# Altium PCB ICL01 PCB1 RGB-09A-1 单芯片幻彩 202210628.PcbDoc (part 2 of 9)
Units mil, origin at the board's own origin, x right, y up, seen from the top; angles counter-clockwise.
Board outline 17436.43 x 6581.89 mil, 2 copper layers (Top Layer, Bottom Layer), stack 65.792 mil thick; 425 components, 516 nets, 1625 pads, 2772 vias.
Unrouted connection lines stored in the file: 1.
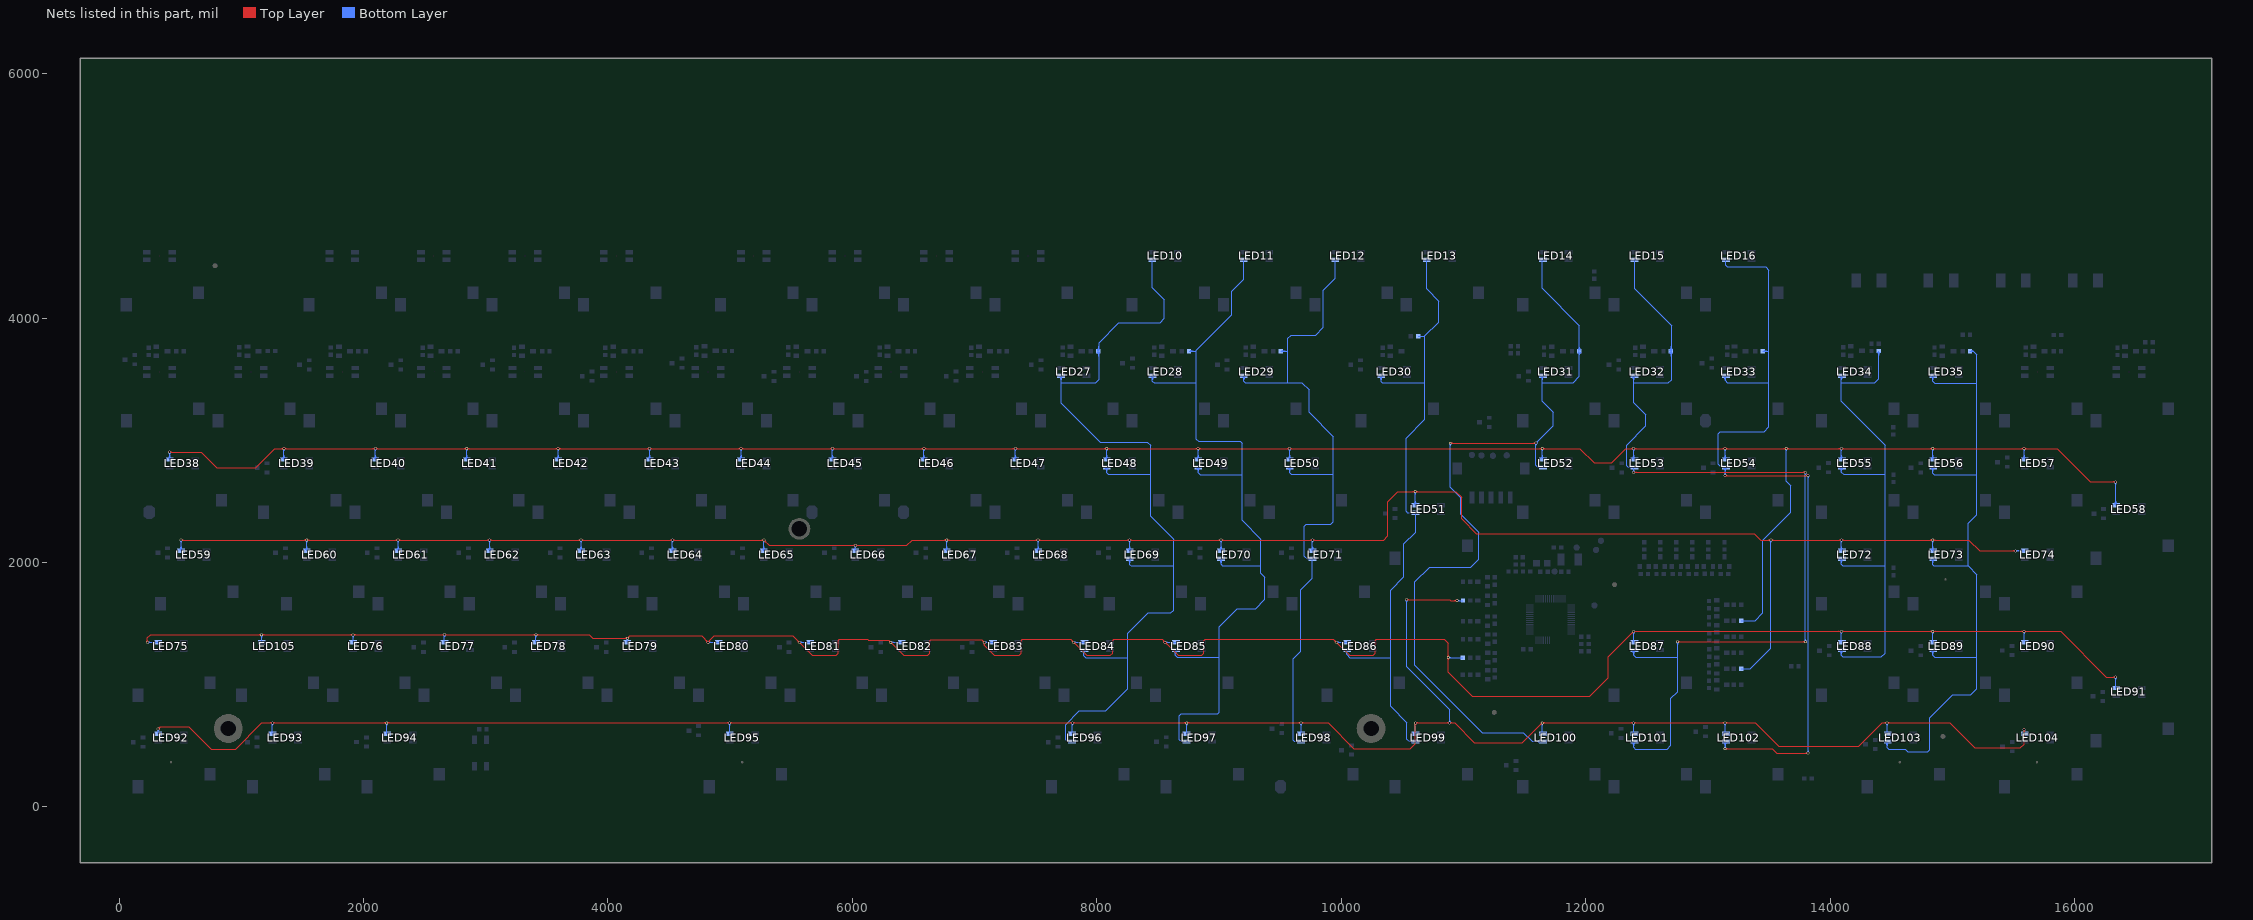
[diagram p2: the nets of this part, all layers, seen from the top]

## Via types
v1: diameter 23.62, hole 15.75, Top Layer to Bottom Layer, tented both sides, 2766 vias
v2: diameter 19.68, hole 11.81, Top Layer to Bottom Layer, tented both sides, 6 vias

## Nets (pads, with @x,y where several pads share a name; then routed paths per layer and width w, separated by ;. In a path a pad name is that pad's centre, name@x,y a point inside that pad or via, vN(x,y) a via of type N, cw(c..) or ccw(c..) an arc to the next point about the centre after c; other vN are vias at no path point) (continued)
BL2: LED38.B LED39.B LED40.B LED41.B LED42.B LED43.B LED44.B LED45.B LED46.B LED47.B LED48.B LED49.B LED50.B LED52.B LED53.B LED54.B LED55.B LED56.B LED57.B LED58.B RR8.2 | length 22619.1
  Top Layer w7.87: v1(414,2902.51) 674.24,2902.51 800.37,2776.38 1117.56,2776.38 1272.69,2931.5 v1(11644.32,2931.47) ; v1@419.57,2896.94 cw(c433.01,2883.5) 433.01,2902.51 cw(c433.01,2921.52) v1@419.57,2908.08 ; 1329.95,2931.5 cw(c1329.95,2912.38) v1@1343.47,2925.9 ; 1330.11,2931.5 ccw(c1330.11,2950.4) v1@1343.47,2937.04 ; v1@1354.61,2925.9 cw(c1368.13,2912.38) 1368.13,2931.5 ; v1@1354.61,2937.04 ccw(c1367.97,2950.4) 1367.97,2931.5 ; 2077.98,2931.5 cw(c2077.98,2912.38) v1@2091.5,2925.9 ; 2078.14,2931.5 ccw(c2078.14,2950.4) v1@2091.5,2937.04 ; v1@2102.64,2925.9 cw(c2116.16,2912.38) 2116.16,2931.5 ; v1@2102.64,2937.04 ccw(c2116,2950.4) 2116,2931.5 ; 2826.01,2931.5 cw(c2826.01,2912.38) v1@2839.53,2925.9 ; 2826.17,2931.5 ccw(c2826.17,2950.4) v1@2839.53,2937.04 ; v1@2850.67,2925.9 cw(c2864.19,2912.38) 2864.19,2931.5 ; v1@2850.67,2937.04 ccw(c2864.03,2950.4) 2864.03,2931.5 ; 3574.05,2931.5 cw(c3574.05,2912.38) v1@3587.57,2925.9 ; 3574.2,2931.5 ccw(c3574.2,2950.4) v1@3587.57,2937.04 ; v1@3598.7,2925.9 cw(c3612.22,2912.38) 3612.22,2931.5 ; v1@3598.7,2937.04 ccw(c3612.06,2950.4) 3612.06,2931.5 ; 4322.08,2931.5 cw(c4322.08,2912.38) v1@4335.6,2925.9 ; 4322.23,2931.5 ccw(c4322.23,2950.4) v1@4335.6,2937.04 ; v1@4346.73,2925.9 cw(c4360.25,2912.38) 4360.25,2931.5 ; v1@4346.73,2937.04 ccw(c4360.1,2950.4) 4360.1,2931.5 ; 5070.11,2931.5 cw(c5070.11,2912.38) v1@5083.63,2925.9 ; 5070.27,2931.5 ccw(c5070.27,2950.4) v1@5083.63,2937.04 ; v1@5094.77,2925.9 cw(c5108.29,2912.38) 5108.29,2931.5 ; v1@5094.77,2937.04 ccw(c5108.13,2950.4) 5108.13,2931.5 ; 5818.14,2931.5 cw(c5818.14,2912.38) v1@5831.66,2925.9 ; 5818.3,2931.5 ccw(c5818.3,2950.4) v1@5831.66,2937.04 ; v1@5842.8,2925.9 cw(c5856.32,2912.38) 5856.32,2931.5 ; v1@5842.8,2937.04 ccw(c5856.16,2950.4) 5856.16,2931.5 ; 6566.17,2931.5 cw(c6566.17,2912.38) v1@6579.69,2925.9 ; 6566.33,2931.5 ccw(c6566.33,2950.4) v1@6579.69,2937.04 ; v1@6590.83,2925.9 cw(c6604.35,2912.38) 6604.35,2931.5 ; v1@6590.83,2937.04 ccw(c6604.19,2950.4) 6604.19,2931.5 ; 7314.2,2931.5 cw(c7314.2,2912.38) v1@7327.72,2925.9 ; 7314.36,2931.5 ccw(c7314.36,2950.4) v1@7327.72,2937.04 ; v1@7338.86,2925.9 cw(c7352.38,2912.38) 7352.38,2931.5 ; v1@7338.86,2937.04 ccw(c7352.22,2950.4) 7352.22,2931.5 ; 8062.23,2931.5 cw(c8062.23,2912.38) v1@8075.76,2925.9 ; 8062.39,2931.5 ccw(c8062.39,2950.4) v1@8075.76,2937.04 ; v1@8086.89,2925.9 cw(c8100.41,2912.38) 8100.41,2931.5 ; v1@8086.89,2937.04 ccw(c8100.25,2950.4) 8100.25,2931.5 ; 8810.27,2931.5 cw(c8810.27,2912.38) v1@8823.79,2925.9 ; 8810.42,2931.5 ccw(c8810.42,2950.4) v1@8823.79,2937.04 ; v1@8834.92,2925.9 cw(c8848.44,2912.38) 8848.44,2931.5 ; v1@8834.92,2937.04 ccw(c8848.28,2950.4) 8848.28,2931.5 ; 9558.3,2931.5 cw(c9558.3,2912.38) v1@9571.82,2925.9 ; 9558.46,2931.5 ccw(c9558.46,2950.4) v1@9571.82,2937.04 ; v1@9582.95,2925.9 cw(c9596.47,2912.38) 9596.47,2931.5 ; v1@9582.95,2937.04 ccw(c9596.32,2950.4) 9596.32,2931.5 ; 11625.23,2931.5 cw(c11625.23,2912.38) v1@11638.75,2925.9 ; 11625.38,2931.5 ccw(c11625.38,2950.4) v1@11638.75,2937.04 ; v1(11644.32,2931.47) 11950.51,2931.47 12067.84,2814.14 12211.84,2814.14 12329.21,2931.5 v1(13640.43,2931.5) 15856,2931.5 16128.57,2658.93 v1(16335.26,2658.93) ; v1@11649.88,2925.9 cw(c11663.32,2912.46) 11663.32,2931.47 cw(c11663.32,2950.48) v1@11649.88,2937.04 ; 12373.26,2931.5 cw(c12373.26,2912.38) v1@12386.78,2925.9 ; 12373.42,2931.5 ccw(c12373.42,2950.4) v1@12386.78,2937.04 ; v1@12397.91,2925.9 cw(c12411.43,2912.38) 12411.43,2931.5 ; v1@12397.91,2937.04 ccw(c12411.28,2950.4) 12411.28,2931.5 ; 13121.29,2931.5 cw(c13121.29,2912.38) v1@13134.81,2925.9 ; 13121.45,2931.5 ccw(c13121.45,2950.4) v1@13134.81,2937.04 ; v1@13145.95,2925.9 cw(c13159.47,2912.38) 13159.47,2931.5 ; v1@13145.95,2937.04 ccw(c13159.31,2950.4) 13159.31,2931.5 ; v1@13634.86,2925.94 ccw(c13621.42,2912.49) 13621.42,2931.5 ccw(c13621.42,2950.51) v1@13634.86,2937.07 ; v1@13646,2925.94 cw(c13659.44,2912.49) 13659.44,2931.5 cw(c13659.44,2950.51) v1@13646,2937.07 ; 14072.08,2931.5 cw(c14072.08,2912.38) v1@14085.6,2925.9 ; 14072.23,2931.5 ccw(c14072.23,2950.4) v1@14085.6,2937.04 ; v1@14096.73,2925.9 cw(c14110.25,2912.38) 14110.25,2931.5 ; v1@14096.73,2937.04 ccw(c14110.1,2950.4) 14110.1,2931.5 ; 14820.11,2931.5 cw(c14820.11,2912.38) v1@14833.63,2925.9 ; 14820.27,2931.5 ccw(c14820.27,2950.4) v1@14833.63,2937.04 ; v1@14844.77,2925.9 cw(c14858.29,2912.38) 14858.29,2931.5 ; v1@14844.77,2937.04 ccw(c14858.13,2950.4) 14858.13,2931.5 ; 15567.96,2931.5 ccw(c15567.96,2950.88) v1@15581.66,2937.18 ; 15568.48,2931.5 cw(c15568.48,2912.86) v1@15581.66,2926.04 ; v1@15592.8,2926.04 cw(c15605.98,2912.86) 15605.98,2931.5 ; v1@15592.8,2937.18 ccw(c15606.5,2950.88) 15606.5,2931.5 ; v1@16329.69,2653.36 ccw(c16316.25,2639.92) 16316.25,2658.93 ccw(c16316.25,2677.94) v1@16329.69,2664.5
  Bottom Layer w7.87: LED38.B@404.26,2852.46 ccw(c380.73,2875.98) 414,2875.98 ccw(c447.27,2875.98) LED38.B@423.74,2852.46 ; v1@408.43,2896.94 cw(c394.99,2883.5) 414,2883.5 cw(c433.01,2883.5) v1@419.57,2896.94 ; LED38.B@414,2842.72 v1(414,2902.51) ; LED39.B@1339.3,2852.46 ccw(c1315.77,2875.98) 1349.04,2875.98 ccw(c1382.31,2875.98) LED39.B@1358.78,2852.46 ; v1@1343.47,2925.9 cw(c1330.03,2912.46) 1349.04,2912.46 cw(c1368.05,2912.46) v1@1354.61,2925.9 ; LED39.B@1349.04,2842.72 v1(1349.04,2931.47) ; LED40.B@2087.33,2852.46 ccw(c2063.8,2875.98) 2097.07,2875.98 ccw(c2130.34,2875.98) LED40.B@2106.81,2852.46 ; v1@2091.5,2925.9 cw(c2078.06,2912.46) 2097.07,2912.46 cw(c2116.08,2912.46) v1@2102.64,2925.9 ; LED40.B@2097.07,2842.72 v1(2097.07,2931.47) ; LED41.B@2835.36,2852.46 ccw(c2811.84,2875.98) 2845.1,2875.98 ccw(c2878.37,2875.98) LED41.B@2854.85,2852.46 ; v1@2839.53,2925.9 cw(c2826.09,2912.46) 2845.1,2912.46 cw(c2864.11,2912.46) v1@2850.67,2925.9 ; LED41.B@2845.1,2842.72 v1(2845.1,2931.47) ; LED42.B@3583.39,2852.46 ccw(c3559.87,2875.98) 3593.13,2875.98 ccw(c3626.4,2875.98) LED42.B@3602.88,2852.46 ; v1@3587.57,2925.9 cw(c3574.12,2912.46) 3593.13,2912.46 cw(c3612.14,2912.46) v1@3598.7,2925.9 ; LED42.B@3593.13,2842.72 v1(3593.13,2931.47) ; LED43.B@4331.42,2852.46 ccw(c4307.9,2875.98) 4341.17,2875.98 ccw(c4374.43,2875.98) LED43.B@4350.91,2852.46 ; v1@4335.6,2925.9 cw(c4322.16,2912.46) 4341.17,2912.46 cw(c4360.17,2912.46) v1@4346.73,2925.9 ; LED43.B@4341.17,2842.72 v1(4341.17,2931.47) ; LED44.B@5079.45,2852.46 ccw(c5055.93,2875.98) 5089.2,2875.98 ccw(c5122.46,2875.98) LED44.B@5098.94,2852.46 ; v1@5083.63,2925.9 cw(c5070.19,2912.46) 5089.2,2912.46 cw(c5108.21,2912.46) v1@5094.77,2925.9 ; LED44.B@5089.2,2842.72 v1(5089.2,2931.47) ; LED45.B@5827.48,2852.46 ccw(c5803.96,2875.98) 5837.23,2875.98 ccw(c5870.5,2875.98) LED45.B@5846.97,2852.46 ; v1@5831.66,2925.9 cw(c5818.22,2912.46) 5837.23,2912.46 cw(c5856.24,2912.46) v1@5842.8,2925.9 ; LED45.B@5837.23,2842.72 v1(5837.23,2931.47) ; LED46.B@6575.52,2852.46 ccw(c6551.99,2875.98) 6585.26,2875.98 ccw(c6618.53,2875.98) LED46.B@6595,2852.46 ; v1@6579.69,2925.9 cw(c6566.25,2912.46) 6585.26,2912.46 cw(c6604.27,2912.46) v1@6590.83,2925.9 ; LED46.B@6585.26,2842.72 v1(6585.26,2931.47) ; LED47.B@7323.55,2852.46 ccw(c7300.02,2875.98) 7333.29,2875.98 ccw(c7366.56,2875.98) LED47.B@7343.03,2852.46 ; v1@7327.72,2925.9 cw(c7314.28,2912.46) 7333.29,2912.46 cw(c7352.3,2912.46) v1@7338.86,2925.9 ; LED47.B@7333.29,2842.72 v1(7333.29,2931.47) ; LED48.B@8071.58,2852.46 ccw(c8048.06,2875.98) 8081.32,2875.98 ccw(c8114.59,2875.98) LED48.B@8091.07,2852.46 ; v1@8075.76,2925.9 cw(c8062.31,2912.46) 8081.32,2912.46 cw(c8100.33,2912.46) v1@8086.89,2925.9 ; LED48.B@8081.32,2842.72 v1(8081.32,2931.47) ; LED49.B@8819.61,2852.46 ccw(c8796.09,2875.98) 8829.35,2875.98 ccw(c8862.62,2875.98) LED49.B@8839.1,2852.46 ; v1@8823.79,2925.9 cw(c8810.34,2912.46) 8829.35,2912.46 cw(c8848.36,2912.46) v1@8834.92,2925.9 ; LED49.B@8829.35,2842.72 v1(8829.35,2931.47) ; LED50.B@9567.64,2852.46 ccw(c9544.12,2875.98) 9577.39,2875.98 ccw(c9610.65,2875.98) LED50.B@9587.13,2852.46 ; v1@9571.82,2925.9 cw(c9558.38,2912.46) 9577.39,2912.46 cw(c9596.4,2912.46) v1@9582.95,2925.9 ; LED50.B@9577.39,2842.72 v1(9577.39,2931.47) ; LED52.B@11634.57,2852.46 ccw(c11611.05,2875.98) 11644.32,2875.98 ccw(c11677.58,2875.98) LED52.B@11654.06,2852.46 ; v1@11638.75,2925.9 cw(c11625.31,2912.46) 11644.32,2912.46 cw(c11663.32,2912.46) v1@11649.88,2925.9 ; LED52.B@11644.32,2842.72 v1(11644.32,2931.47) ; LED53.B@12382.6,2852.46 ccw(c12359.08,2875.98) 12392.35,2875.98 ccw(c12425.61,2875.98) LED53.B@12402.09,2852.46 ; v1@12386.78,2925.9 cw(c12373.34,2912.46) 12392.35,2912.46 cw(c12411.36,2912.46) v1@12397.91,2925.9 ; LED53.B@12392.35,2842.72 v1(12392.35,2931.47) ; LED54.B@13130.63,2852.46 ccw(c13107.11,2875.98) 13140.38,2875.98 ccw(c13173.65,2875.98) LED54.B@13150.12,2852.46 ; v1@13134.81,2925.9 cw(c13121.37,2912.46) 13140.38,2912.46 cw(c13159.39,2912.46) v1@13145.95,2925.9 ; LED54.B@13140.38,2842.72 v1(13140.38,2931.47) ; RR8.2@13272.34,1523.08 13385.24,1523.08 13450.47,1588.31 13450.47,2183.47 13676.57,2409.57 13676.57,2628.64 13640.43,2664.77 v1(13640.43,2931.5) ; v1@13634.86,2925.94 cw(c13621.42,2912.49) 13640.43,2912.49 cw(c13659.44,2912.49) v1@13646,2925.94 ; LED55.B@14081.42,2852.46 ccw(c14057.9,2875.98) 14091.17,2875.98 ccw(c14124.43,2875.98) LED55.B@14100.91,2852.46 ; v1@14085.6,2925.9 cw(c14072.16,2912.46) 14091.17,2912.46 cw(c14110.17,2912.46) v1@14096.73,2925.9 ; LED55.B@14091.17,2842.72 v1(14091.17,2931.47) ; LED56.B@14829.45,2852.46 ccw(c14805.93,2875.98) 14839.2,2875.98 ccw(c14872.46,2875.98) LED56.B@14848.94,2852.46 ; v1@14833.63,2925.9 cw(c14820.19,2912.46) 14839.2,2912.46 cw(c14858.21,2912.46) v1@14844.77,2925.9 ; LED56.B@14839.2,2842.72 v1(14839.2,2931.47) ; LED57.B@15577.48,2852.46 ccw(c15553.96,2875.98) 15587.23,2875.98 ccw(c15620.5,2875.98) LED57.B@15596.97,2852.46 ; v1@15581.66,2926.04 cw(c15568.22,2912.6) 15587.23,2912.6 cw(c15606.24,2912.6) v1@15592.8,2926.04 ; LED57.B@15587.23,2842.72 v1(15587.23,2931.61) ; LED58.B@16325.52,2478.45 ccw(c16302,2501.97) 16335.26,2501.97 ccw(c16368.53,2501.97) LED58.B@16345.01,2478.45 ; v1@16329.69,2653.36 cw(c16316.25,2639.92) 16335.26,2639.92 cw(c16354.27,2639.92) v1@16340.83,2653.36 ; LED58.B@16335.26,2468.7 v1(16335.26,2658.93)
BL3: LED51.B LED59.B LED60.B LED61.B LED62.B LED63.B LED64.B LED65.B LED66.B LED67.B LED68.B LED69.B LED70.B LED71.B LED72.B LED73.B LED74.B RR11.2 | length 20735.3
  Top Layer w7.87: v1@506.86,2183.47 v1@5276.37,2183.47 ; v1@513.07,2177.95 cw(c526.4,2164.62) 526.4,2183.47 ; v1@513.07,2189.09 ccw(c526.62,2202.64) 526.62,2183.47 ; 1516.65,2183.47 ccw(c1516.65,2203.03) v1@1530.48,2189.2 ; 1517.43,2183.47 cw(c1517.43,2165.01) v1@1530.48,2178.06 ; v1@1541.62,2178.06 cw(c1554.67,2165.01) 1554.67,2183.47 ; v1@1541.62,2189.2 ccw(c1555.44,2203.03) 1555.44,2183.47 ; 2264.68,2183.47 ccw(c2264.68,2203.03) v1@2278.51,2189.2 ; 2265.46,2183.47 cw(c2265.46,2165.01) v1@2278.51,2178.06 ; v1@2289.65,2178.06 cw(c2302.7,2165.01) 2302.7,2183.47 ; v1@2289.65,2189.2 ccw(c2303.48,2203.03) 2303.48,2183.47 ; 3012.71,2183.47 ccw(c3012.71,2203.03) v1@3026.54,2189.2 ; 3013.49,2183.47 cw(c3013.49,2165.01) v1@3026.54,2178.06 ; v1@3037.68,2178.06 cw(c3050.73,2165.01) 3050.73,2183.47 ; v1@3037.68,2189.2 ccw(c3051.51,2203.03) 3051.51,2183.47 ; 3760.74,2183.47 ccw(c3760.74,2203.03) v1@3774.57,2189.2 ; 3761.52,2183.47 cw(c3761.52,2165.01) v1@3774.57,2178.06 ; v1@3785.71,2178.06 cw(c3798.76,2165.01) 3798.76,2183.47 ; v1@3785.71,2189.2 ccw(c3799.54,2203.03) 3799.54,2183.47 ; 4509.05,2183.47 ccw(c4509.05,2202.65) v1@4522.61,2189.09 ; 4509.28,2183.47 cw(c4509.28,2164.63) v1@4522.61,2177.95 ; v1@4533.74,2177.95 cw(c4547.07,2164.63) 4547.07,2183.47 ; v1@4533.74,2189.09 ccw(c4547.3,2202.65) 4547.3,2183.47 ; 5256.81,2183.47 ccw(c5256.81,2203.03) v1@5270.64,2189.2 ; 5257.58,2183.47 cw(c5257.58,2165.01) v1@5270.64,2178.06 ; v1@5276.21,2175.76 cw(c5276.21,2156.75) 5289.65,2170.19 cw(c5303.09,2183.63) v1@5284.08,2183.63 ; v1(5276.21,2183.63) v1@5276.37,2183.47 ; 6003.83,2139.07 ccw(c6003.83,2160.07) v1@6018.67,2145.22 ; 6006.64,2139.07 cw(c6006.64,2122.05) v1@6018.67,2134.09 ; v1@6029.81,2134.09 cw(c6041.85,2122.05) 6041.85,2139.07 ; v1@6029.81,2145.22 ccw(c6044.66,2160.07) 6044.66,2139.07 ; 6752.87,2183.47 ccw(c6752.87,2203.03) v1@6766.7,2189.2 ; 6753.65,2183.47 cw(c6753.65,2165.01) v1@6766.7,2178.06 ; v1@6777.84,2178.06 cw(c6790.89,2165.01) 6790.89,2183.47 ; v1@6777.84,2189.2 ccw(c6791.67,2203.03) 6791.67,2183.47 ; 7500.9,2183.47 ccw(c7500.9,2203.03) v1@7514.73,2189.2 ; 7501.68,2183.47 cw(c7501.68,2165.01) v1@7514.73,2178.06 ; v1@7525.87,2178.06 cw(c7538.92,2165.01) 7538.92,2183.47 ; v1@7525.87,2189.2 ccw(c7539.7,2203.03) 7539.7,2183.47 ; 8248.93,2183.47 ccw(c8248.93,2203.03) v1@8262.76,2189.2 ; 8249.71,2183.47 cw(c8249.71,2165.01) v1@8262.76,2178.06 ; v1@8273.9,2178.06 cw(c8286.95,2165.01) 8286.95,2183.47 ; v1@8273.9,2189.2 ccw(c8287.73,2203.03) 8287.73,2183.47 ; 8996.96,2183.47 ccw(c8996.96,2203.03) v1@9010.79,2189.2 ; 8997.74,2183.47 cw(c8997.74,2165.01) v1@9010.79,2178.06 ; v1@9021.93,2178.06 cw(c9034.98,2165.01) 9034.98,2183.47 ; v1@9021.93,2189.2 ccw(c9035.76,2203.03) 9035.76,2183.47 ; 9745,2183.47 ccw(c9745,2203.03) v1@9758.83,2189.2 ; 9745.77,2183.47 cw(c9745.77,2165.01) v1@9758.83,2178.06 ; v1@9769.96,2178.06 cw(c9783.02,2165.01) 9783.02,2183.47 ; v1@9769.96,2189.2 ccw(c9783.79,2203.03) 9783.79,2183.47 ; 9973.06,2183.51 9973.1,2183.47 ; 10586.13,2579.14 ccw(c10586.13,2598.64) v1@10599.92,2584.85 ; 10586.83,2579.14 cw(c10586.83,2560.62) v1@10599.92,2573.72 ; v1@10611.06,2573.72 cw(c10624.15,2560.62) 10624.15,2579.14 ; v1@10611.06,2584.85 ccw(c10624.84,2598.64) 10624.84,2579.14 ; v1@13508.88,2177.9 ccw(c13495.44,2164.46) 13495.44,2183.47 ccw(c13495.44,2202.48) v1@13508.88,2189.04 ; v1@13520.01,2177.9 cw(c13533.46,2164.46) 13533.46,2183.47 cw(c13533.46,2202.48) v1@13520.01,2189.04 ; 14071.77,2183.47 ccw(c14071.77,2203.03) v1@14085.6,2189.2 ; 14072.54,2183.47 cw(c14072.54,2165.01) v1@14085.6,2178.06 ; v1@14096.73,2178.06 cw(c14109.79,2165.01) 14109.79,2183.47 ; v1@14096.73,2189.2 ccw(c14110.56,2203.03) 14110.56,2183.47 ; 14819.8,2183.47 ccw(c14819.8,2203.03) v1@14833.63,2189.2 ; 14820.58,2183.47 cw(c14820.58,2165.01) v1@14833.63,2178.06 ; v1@14844.77,2178.06 cw(c14857.82,2165.01) 14857.82,2183.47 ; v1@14844.77,2189.2 ccw(c14858.59,2203.03) 14858.59,2183.47 ; v1@15510.05,2089.12 ccw(c15496.61,2075.68) 15496.61,2094.69 ccw(c15496.61,2113.7) v1@15510.05,2100.25 ; v1(15515.62,2094.69) 15222.45,2094.69 15133.67,2183.47 v1(13514.45,2183.47) 13430.93,2183.47 13377.64,2236.77 11105.33,2236.77 10983.84,2358.26 10983.84,2532.98 10937.68,2579.14 10462.28,2579.14 10381.75,2498.61 10381.75,2218.03 10347.2,2183.47 9973.1,2183.47 ; v1@5276.37,2183.47 5320.77,2139.07 6445.04,2139.07 6489.44,2183.47 9973.1,2183.47
  Bottom Layer w7.87: LED59.B@497.76,2104.43 ccw(c474.24,2127.95) 507.5,2127.95 ccw(c540.77,2127.95) LED59.B@517.25,2104.43 ; v1@501.94,2177.95 cw(c488.49,2164.51) 507.5,2164.51 cw(c526.51,2164.51) v1@513.07,2177.95 ; LED59.B@507.5,2094.69 v1(507.5,2183.52) ; LED60.B@1526.3,2104.43 ccw(c1502.78,2127.95) 1536.05,2127.95 ccw(c1569.31,2127.95) LED60.B@1545.79,2104.43 ; v1@1530.48,2178.06 cw(c1517.04,2164.62) 1536.05,2164.62 cw(c1555.06,2164.62) v1@1541.62,2178.06 ; LED60.B@1536.05,2094.69 v1(1536.05,2183.63) ; LED61.B@2274.34,2104.43 ccw(c2250.81,2127.95) 2284.08,2127.95 ccw(c2317.35,2127.95) LED61.B@2293.82,2104.43 ; v1@2278.51,2178.06 cw(c2265.07,2164.62) 2284.08,2164.62 cw(c2303.09,2164.62) v1@2289.65,2178.06 ; LED61.B@2284.08,2094.69 v1(2284.08,2183.63) ; LED62.B@3022.37,2104.43 ccw(c2998.84,2127.95) 3032.11,2127.95 ccw(c3065.38,2127.95) LED62.B@3041.85,2104.43 ; v1@3026.54,2178.06 cw(c3013.1,2164.62) 3032.11,2164.62 cw(c3051.12,2164.62) v1@3037.68,2178.06 ; LED62.B@3032.11,2094.69 v1(3032.11,2183.63) ; LED63.B@3770.4,2104.43 ccw(c3746.88,2127.95) 3780.14,2127.95 ccw(c3813.41,2127.95) LED63.B@3789.89,2104.43 ; v1@3774.57,2178.06 cw(c3761.13,2164.62) 3780.14,2164.62 cw(c3799.15,2164.62) v1@3785.71,2178.06 ; LED63.B@3780.14,2094.69 v1(3780.14,2183.63) ; LED64.B@4518.43,2104.43 ccw(c4494.91,2127.95) 4528.17,2127.95 ccw(c4561.44,2127.95) LED64.B@4537.92,2104.43 ; v1@4522.61,2177.95 cw(c4509.16,2164.51) 4528.17,2164.51 cw(c4547.18,2164.51) v1@4533.74,2177.95 ; LED64.B@4528.17,2094.69 v1(4528.17,2183.52) ; LED65.B@5266.46,2104.43 ccw(c5242.94,2127.95) 5276.21,2127.95 ccw(c5309.47,2127.95) LED65.B@5285.95,2104.43 ; v1@5270.64,2178.06 cw(c5257.2,2164.62) 5276.21,2164.62 cw(c5295.21,2164.62) v1@5281.77,2178.06 ; LED65.B@5276.21,2094.69 v1(5276.21,2183.63) ; v1@6018.67,2134.09 cw(c6005.25,2120.66) 6024.24,2120.66 ; LED66.B@6024.24,2094.69 v1(6024.24,2139.65) ; 6024.24,2120.63 cw(c6043.27,2120.63) v1@6029.81,2134.09 ; LED67.B@6762.52,2104.43 ccw(c6739,2127.95) 6772.27,2127.95 ccw(c6805.54,2127.95) LED67.B@6782.01,2104.43 ; v1@6766.7,2178.06 cw(c6753.26,2164.62) 6772.27,2164.62 cw(c6791.28,2164.62) v1@6777.84,2178.06 ; LED67.B@6772.27,2094.69 v1(6772.27,2183.63) ; LED68.B@7510.56,2104.43 ccw(c7487.03,2127.95) 7520.3,2127.95 ccw(c7553.57,2127.95) LED68.B@7530.04,2104.43 ; v1@7514.73,2178.06 cw(c7501.29,2164.62) 7520.3,2164.62 cw(c7539.31,2164.62) v1@7525.87,2178.06 ; LED68.B@7520.3,2094.69 v1(7520.3,2183.63) ; LED69.B@8258.59,2104.43 ccw(c8235.06,2127.95) 8268.33,2127.95 ccw(c8301.6,2127.95) LED69.B@8278.07,2104.43 ; v1@8262.76,2178.06 cw(c8249.32,2164.62) 8268.33,2164.62 cw(c8287.34,2164.62) v1@8273.9,2178.06 ; LED69.B@8268.33,2094.69 v1(8268.33,2183.63) ; LED70.B@9006.62,2104.43 ccw(c8983.1,2127.95) 9016.36,2127.95 ccw(c9049.63,2127.95) LED70.B@9026.11,2104.43 ; v1@9010.79,2178.06 cw(c8997.35,2164.62) 9016.36,2164.62 cw(c9035.37,2164.62) v1@9021.93,2178.06 ; LED70.B@9016.36,2094.69 v1(9016.36,2183.63) ; LED71.B@9754.65,2104.43 ccw(c9731.13,2127.95) 9764.39,2127.95 ccw(c9797.66,2127.95) LED71.B@9774.14,2104.43 ; v1@9758.83,2178.06 cw(c9745.38,2164.62) 9764.39,2164.62 cw(c9783.4,2164.62) v1@9769.96,2178.06 ; LED71.B@9764.39,2094.69 v1(9764.39,2183.63) ; LED51.B@10595.74,2478.38 ccw(c10572.22,2501.91) 10605.49,2501.91 ccw(c10638.76,2501.91) LED51.B@10615.23,2478.38 ; v1@10599.92,2573.72 cw(c10586.48,2560.28) 10605.49,2560.28 cw(c10624.5,2560.28) v1@10611.06,2573.72 ; LED51.B@10605.49,2468.64 v1(10605.49,2579.29) ; RR11.2@13272.34,1129.41 13345.47,1129.41 13514.45,1298.39 v1(13514.45,2183.47) ; v1@13508.88,2177.9 cw(c13495.44,2164.46) 13514.45,2164.46 cw(c13533.46,2164.46) v1@13520.01,2177.9 ; LED72.B@14081.42,2104.43 ccw(c14057.9,2127.95) 14091.17,2127.95 ccw(c14124.43,2127.95) LED72.B@14100.91,2104.43 ; v1@14085.6,2178.06 cw(c14072.16,2164.62) 14091.17,2164.62 cw(c14110.17,2164.62) v1@14096.73,2178.06 ; LED72.B@14091.17,2094.69 v1(14091.17,2183.63) ; LED73.B@14829.45,2104.43 ccw(c14805.93,2127.95) 14839.2,2127.95 ccw(c14872.46,2127.95) LED73.B@14848.94,2104.43 ; v1@14833.63,2178.06 cw(c14820.19,2164.62) 14839.2,2164.62 cw(c14858.21,2164.62) v1@14844.77,2178.06 ; LED73.B@14839.2,2094.69 v1(14839.2,2183.63) ; v1(15515.62,2094.69) LED74.B@15587.23,2094.69 ; v1@15521.19,2089.12 cw(c15534.63,2075.68) 15534.63,2094.69 cw(c15534.63,2113.7) v1@15521.19,2100.25 ; LED74.B@15563.71,2084.94 ccw(c15540.18,2061.42) 15540.18,2094.69 ccw(c15540.18,2127.95) LED74.B@15563.71,2104.43
BL4: LED75.B LED76.B LED77.B LED78.B LED79.B LED80.B LED81.B LED82.B LED83.B LED84.B LED85.B LED86.B LED87.B LED88.B LED89.B LED90.B LED91.B LED105.B RR14.2 | length 21238
  Top Layer w7.87: v1@226.11,1352.22 ccw(c212.67,1365.67) 231.68,1365.67 ccw(c250.69,1365.67) v1@237.24,1352.22 ; v1(231.68,1346.66) 231.68,1382.31 258.09,1408.73 1826.16,1408.73 ; 1147.6,1408.73 cw(c1147.6,1389.23) v1@1161.39,1403.02 ; 1148.29,1408.73 ccw(c1148.29,1427.25) v1@1161.39,1414.15 ; v1@1172.52,1403.02 cw(c1186.31,1389.23) 1186.31,1408.73 ; v1@1172.52,1414.15 ccw(c1185.62,1427.25) 1185.62,1408.73 ; 1826.16,1408.49 3411.05,1408.49 3846.06,1408.53 3874.25,1380.34 v1(4159.08,1380.35) 4177.65,1398.92 4766.03,1398.92 v1(4818.29,1346.66) 4870.55,1398.92 5514.06,1398.92 v1(5566.32,1346.66) 5673.14,1239.84 5867.32,1239.84 5884.31,1256.83 5884.31,1360.53 5894.22,1370.44 6124.75,1370.44 6131.78,1363.41 6297.6,1363.41 v1(6314.35,1346.66) 6421.17,1239.84 6615.35,1239.84 6632.34,1256.83 6632.34,1360.53 6640.19,1368.38 7058.27,1368.38 v1(7079.99,1346.66) 7079.99,1320.94 7161.09,1239.84 7363.38,1239.84 7380.37,1256.83 7380.37,1360.53 7390.29,1370.44 7786.63,1370.44 v1(7810.42,1346.66) 7917.23,1239.84 8111.41,1239.84 8128.4,1256.83 8128.4,1360.53 8138.32,1370.44 8534.66,1370.44 v1(8558.45,1346.66) 8665.26,1239.84 8859.44,1239.84 8876.43,1256.83 8876.43,1360.53 8886.35,1370.44 9936.24,1370.44 v1(9960.02,1346.66) 10067.4,1239.28 10260.46,1239.28 10278.01,1256.83 10278.01,1360.53 10287.92,1370.44 10844.09,1370.44 10875.42,1339.11 10875.42,1103.93 11072.52,906.84 12033.91,906.84 12185.48,1058.4 12185.48,1228.61 v1(12392.35,1435.48) 15887.02,1435.44 16260.03,1062.43 v1(16335.33,1062.43) ; 1895.02,1408.49 cw(c1895.02,1388.13) v1@1909.42,1402.53 ; 1896.93,1408.49 ccw(c1896.93,1426.15) v1@1909.42,1413.66 ; v1@1920.55,1402.53 cw(c1934.94,1388.13) 1934.94,1408.49 ; v1@1920.55,1413.66 ccw(c1933.04,1426.15) 1933.04,1408.49 ; 2639.83,1408.49 ccw(c2639.83,1433.41) v1@2657.45,1415.79 ; 2648.18,1408.49 cw(c2648.18,1395.39) v1@2657.45,1404.65 ; v1@2668.58,1404.65 cw(c2677.85,1395.39) 2677.85,1408.49 ; v1@2668.58,1415.79 ccw(c2686.2,1433.41) 2686.2,1408.49 ; 3391.94,1408.49 ccw(c3391.94,1427.64) v1@3405.48,1414.1 ; 3392.14,1408.49 cw(c3392.14,1389.62) v1@3405.48,1402.96 ; v1@3416.62,1402.96 cw(c3430.06,1389.52) 3430.06,1408.53 cw(c3430.06,1427.54) v1@3416.62,1414.1 ; 4140.06,1380.34 ccw(c4140.06,1399.37) v1@4153.51,1385.91 ; 4140.08,1380.34 cw(c4140.08,1361.35) v1@4153.51,1374.78 ; v1@4159.08,1388.22 ccw(c4159.08,1407.24) 4172.53,1393.79 ; v1@4166.95,1380.35 cw(c4185.95,1380.35) 4172.52,1393.78 ; v1@4810.42,1346.66 ccw(c4791.41,1346.66) 4804.85,1360.1 ccw(c4818.29,1373.54) 4818.29,1354.53 ccw(c4818.29,1373.54) 4831.73,1360.1 ccw(c4845.17,1346.66) v1@4826.16,1346.66 ; v1@5558.45,1346.66 ccw(c5539.44,1346.66) 5552.88,1360.1 ccw(c5566.32,1373.54) v1@5566.32,1354.53 ; v1@5566.32,1338.78 cw(c5566.32,1319.77) 5579.76,1333.21 cw(c5593.2,1346.66) v1@5574.2,1346.66 ; v1@6306.48,1346.66 ccw(c6287.47,1346.66) 6300.91,1360.1 ccw(c6314.35,1373.54) v1@6314.35,1354.53 ; v1@6314.35,1338.78 cw(c6314.35,1319.77) 6327.79,1333.21 cw(c6341.24,1346.66) v1@6322.23,1346.66 ; v1@7072.12,1346.66 ccw(c7053.11,1346.66) 7066.55,1360.1 ccw(c7079.99,1373.54) v1@7079.99,1354.53 ; v1@7074.42,1341.09 cw(c7060.98,1327.65) 7079.99,1327.65 cw(c7099,1327.65) v1@7085.56,1341.09 ; v1@7802.54,1346.66 ccw(c7783.53,1346.66) 7796.97,1360.1 ccw(c7810.42,1373.54) v1@7810.42,1354.53 ; v1@7810.42,1338.78 cw(c7810.42,1319.77) 7823.86,1333.21 cw(c7837.3,1346.66) v1@7818.29,1346.66 ; v1@8550.57,1346.66 ccw(c8531.56,1346.66) 8545.01,1360.1 ccw(c8558.45,1373.54) v1@8558.45,1354.53 ; v1@8558.45,1338.78 cw(c8558.45,1319.77) 8571.89,1333.21 cw(c8585.33,1346.66) v1@8566.32,1346.66 ; v1@9952.15,1346.66 ccw(c9933.14,1346.66) 9946.58,1360.1 ccw(c9960.02,1373.54) v1@9960.02,1354.53 ; v1@9960.02,1338.78 cw(c9960.02,1319.77) 9973.46,1333.21 cw(c9986.91,1346.66) v1@9967.9,1346.66 ; v1@10869.5,1216.02 cw(c10855.2,1201.72) 10875.42,1201.72 ; v1@10869.5,1227.15 ccw(c10855.2,1241.45) 10875.42,1241.45 ; 10875.42,1203.43 cw(c10893.22,1203.43) v1@10880.64,1216.02 ; 10875.42,1239.74 ccw(c10893.22,1239.74) v1@10880.64,1227.15 ; v1@12384.47,1435.48 cw(c12365.46,1435.48) 12378.9,1422.03 cw(c12392.35,1408.59) v1@12392.35,1427.6 ; v1@12397.91,1429.91 cw(c12411.27,1416.55) 12411.27,1435.44 ; v1@12397.91,1441.04 ccw(c12411.44,1454.57) 12411.44,1435.44 ; 14072.07,1435.44 ccw(c14072.07,1454.57) v1@14085.6,1441.04 ; 14072.24,1435.44 cw(c14072.24,1416.55) v1@14085.6,1429.91 ; v1@14096.73,1429.91 cw(c14110.09,1416.55) 14110.09,1435.44 ; v1@14096.73,1441.04 ccw(c14110.26,1454.57) 14110.26,1435.44 ; 14820.1,1435.44 ccw(c14820.1,1454.57) v1@14833.63,1441.04 ; 14820.27,1435.44 cw(c14820.27,1416.55) v1@14833.63,1429.91 ; v1@14844.77,1429.91 cw(c14858.12,1416.55) 14858.12,1435.44 ; v1@14844.77,1441.04 ccw(c14858.29,1454.57) 14858.29,1435.44 ; 15568.13,1435.44 ccw(c15568.13,1454.57) v1@15581.66,1441.04 ; 15568.3,1435.44 cw(c15568.3,1416.55) v1@15581.66,1429.91 ; v1@15592.8,1429.91 cw(c15606.15,1416.55) 15606.15,1435.44 ; v1@15592.8,1441.04 ccw(c15606.32,1454.57) 15606.32,1435.44 ; v1@16329.76,1056.86 ccw(c16316.32,1043.42) 16316.32,1062.43 ccw(c16316.32,1081.44) v1@16329.76,1068
  Bottom Layer w7.87: v1(231.68,1346.66) LED75.B@320.5,1346.66 ; v1@237.24,1341.09 cw(c250.69,1327.65) 250.69,1346.66 cw(c250.69,1365.67) v1@237.24,1352.22 ; v1@1161.39,1403.02 cw(c1147.94,1389.57) 1166.95,1389.57 cw(c1185.96,1389.57) v1@1172.52,1403.02 ; LED105.B@1166.95,1346.66 v1(1166.95,1408.58) ; v1@1909.42,1402.53 cw(c1895.98,1389.09) 1914.98,1389.09 cw(c1933.99,1389.09) v1@1920.55,1402.53 ; LED76.B@1914.98,1346.66 v1(1914.98,1408.1) ; v1@2657.45,1404.65 cw(c2644.01,1391.21) 2663.02,1391.21 cw(c2682.03,1391.21) v1@2668.58,1404.65 ; LED77.B@2663.02,1346.66 v1(2663.02,1410.22) ; v1@3405.48,1402.96 cw(c3392.04,1389.52) 3411.05,1389.52 cw(c3430.06,1389.52) v1@3416.62,1402.96 ; LED78.B@3411.05,1346.66 v1(3411.05,1408.53) ; v1@4153.51,1374.78 cw(c4140.07,1361.34) 4159.08,1361.34 cw(c4178.09,1361.34) v1@4164.65,1374.78 ; LED79.B@4159.08,1346.66 v1(4159.08,1380.35) ; v1(4818.29,1346.66) LED80.B@4907.11,1346.66 ; v1@4823.86,1341.09 cw(c4837.3,1327.65) 4837.3,1346.66 cw(c4837.3,1365.67) v1@4823.86,1352.22 ; v1(5566.32,1346.66) LED81.B@5655.14,1346.66 ; v1@5571.89,1341.09 cw(c5585.33,1327.65) 5585.33,1346.66 cw(c5585.33,1365.67) v1@5571.89,1352.22 ; v1(6314.35,1346.66) LED82.B@6403.17,1346.66 ; v1@6319.92,1341.09 cw(c6333.36,1327.65) 6333.36,1346.66 cw(c6333.36,1365.67) v1@6319.92,1352.22 ; v1(7079.99,1346.66) LED83.B@7151.21,1346.66 ; v1@7085.56,1341.09 cw(c7099,1327.65) 7099,1346.66 cw(c7099,1365.67) v1@7085.56,1352.22 ; v1(7810.42,1346.66) LED84.B@7899.24,1346.66 ; v1@7815.98,1341.09 cw(c7829.43,1327.65) 7829.43,1346.66 cw(c7829.43,1365.67) v1@7815.98,1352.22 ; v1(8558.45,1346.66) LED85.B@8647.27,1346.66 ; v1@8564.02,1341.09 cw(c8577.46,1327.65) 8577.46,1346.66 cw(c8577.46,1365.67) v1@8564.02,1352.22 ; v1(9960.02,1346.66) LED86.B@10048.84,1346.66 ; v1@9965.59,1341.09 cw(c9979.03,1327.65) 9979.03,1346.66 cw(c9979.03,1365.67) v1@9965.59,1352.22 ; v1(10875.07,1221.58) RR14.2@10995.09,1221.58 ; v1@10880.64,1216.02 cw(c10894.08,1202.57) 10894.08,1221.58 cw(c10894.08,1240.59) v1@10880.64,1227.15 ; v1@12386.78,1429.91 cw(c12373.34,1416.47) 12392.35,1416.47 cw(c12411.36,1416.47) v1@12397.91,1429.91 ; LED87.B@12392.35,1346.66 v1(12392.35,1435.48) ; v1@14085.6,1429.91 cw(c14072.16,1416.47) 14091.17,1416.47 cw(c14110.17,1416.47) v1@14096.73,1429.91 ; LED88.B@14091.17,1346.66 v1(14091.17,1435.48) ; v1@14833.63,1429.91 cw(c14820.19,1416.47) 14839.2,1416.47 cw(c14858.21,1416.47) v1@14844.77,1429.91 ; LED89.B@14839.2,1346.66 v1(14839.2,1435.48) ; v1@15581.66,1429.91 cw(c15568.22,1416.47) 15587.23,1416.47 cw(c15606.24,1416.47) v1@15592.8,1429.91 ; LED90.B@15587.23,1346.66 v1(15587.23,1435.48) ; v1@16329.76,1056.86 cw(c16316.5,1043.59) 16335.26,1043.59 ; LED91.B@16335.26,972.64 v1(16335.33,1062.43) ; 16335.26,1043.25 cw(c16354.52,1043.25) v1@16340.9,1056.86
BL5: LED92.B LED93.B LED94.B LED95.B LED96.B LED97.B LED98.B LED99.B LED100.B LED101.B LED102.B LED103.B LED104.B RR17.2 | length 20206.8
  Top Layer w7.87: v1(320.5,637.13) 338.53,655.16 572.14,655.16 755.91,471.39 953.18,471.39 1169.2,687.41 v1@9670.89,687.41 ; v1@320.5,645 ccw(c320.5,664.01) 333.94,650.57 ccw(c347.38,637.13) v1@328.37,637.13 ; 1236.44,687.41 ccw(c1236.44,706.54) v1@1249.97,693.01 ; 1236.61,687.41 cw(c1236.61,668.52) v1@1249.97,681.88 ; v1@1261.1,681.88 cw(c1274.46,668.52) 1274.46,687.41 ; v1@1261.1,693.01 ccw(c1274.63,706.54) 1274.63,687.41 ; 2171.51,687.41 ccw(c2171.51,706.5) v1@2185.01,693 ; 2171.62,687.41 cw(c2171.62,668.48) v1@2185.01,681.86 ; v1@2196.14,681.86 cw(c2209.53,668.48) 2209.53,687.41 ; v1@2196.14,693 ccw(c2209.64,706.5) 2209.64,687.41 ; 4976.57,687.41 ccw(c4976.57,706.57) v1@4990.13,693.02 ; 4976.79,687.41 cw(c4976.79,668.55) v1@4990.13,681.89 ; v1@5001.26,681.89 cw(c5014.59,668.55) 5014.59,687.41 ; v1@5001.26,693.02 ccw(c5014.81,706.57) 5014.81,687.41 ; 7781.57,687.41 ccw(c7781.57,706.75) v1@7795.24,693.07 ; 7782.04,687.41 cw(c7782.04,668.73) v1@7795.24,681.94 ; v1@7806.38,681.94 cw(c7819.59,668.73) 7819.59,687.41 ; v1@7806.38,693.07 ccw(c7820.05,706.75) 7820.05,687.41 ; 8716.76,687.41 ccw(c8716.76,706.54) v1@8730.28,693.01 ; 8716.92,687.41 cw(c8716.92,668.52) v1@8730.28,681.88 ; v1@8741.42,681.88 cw(c8754.78,668.52) 8754.78,687.41 ; v1@8741.42,693.01 ccw(c8754.94,706.54) 8754.94,687.41 ; 9651.8,687.41 ccw(c9651.8,706.53) v1@9665.32,693.01 ; 9651.96,687.41 cw(c9651.96,668.51) v1@9665.32,681.87 ; v1(9670.89,687.44) 9893.69,687.44 10103.68,477.45 10564.75,477.45 10605.93,518.63 10605.93,687.41 10926.69,687.41 11089.1,525 11481.87,525 11644.28,687.41 13387.48,687.41 13579.41,495.48 14232.95,495.48 14424.88,687.41 14979.01,687.41 15182.79,483.64 15556.97,483.64 15587.23,513.89 v1(15587.23,633.69) ; v1@9676.46,681.87 cw(c9689.9,668.43) 9689.9,687.44 cw(c9689.9,706.45) v1@9676.46,693.01 ; v1(10534.44,1696.57) 10887.58,1696.57 10895.25,1688.9 v1(10945.88,1688.9) ; v1@10540,1691 cw(c10553.45,1677.56) 10553.45,1696.57 cw(c10553.45,1715.58) v1@10540,1702.14 ; v1@10600.36,681.86 cw(c10586.92,668.42) 10605.93,668.42 cw(c10624.94,668.42) 10611.5,681.86 cw(c10624.89,668.46) 10624.89,687.41 ; v1@10611.5,693 ccw(c10624.98,706.48) 10624.98,687.41 ; 10867.41,687.41 ccw(c10867.41,706.6) v1@10880.98,693.03 ; 10867.67,687.41 cw(c10867.67,668.58) v1@10880.98,681.9 ; v1@10892.12,681.9 cw(c10905.43,668.58) 10905.43,687.41 ; v1@10892.12,693.03 ccw(c10905.69,706.6) 10905.69,687.41 ; v1@10940.32,1683.33 ccw(c10926.88,1669.89) 10926.88,1688.9 ccw(c10926.88,1707.91) v1@10940.32,1694.47 ; v1@11636.44,687.44 cw(c11617.43,687.44) 11630.87,674 cw(c11644.32,660.56) v1@11644.32,679.57 ; v1@11649.88,681.87 cw(c11663.25,668.51) 11663.25,687.41 ; v1@11649.88,693.01 ccw(c11663.4,706.53) 11663.4,687.41 ; 12372.91,687.41 ccw(c12372.91,707.02) v1@12386.78,693.15 ; 12373.76,687.41 cw(c12373.76,669) v1@12386.78,682.02 ; v1@12397.91,682.02 cw(c12410.93,669) 12410.93,687.41 ; v1@12397.91,693.15 ccw(c12411.78,707.02) 12411.78,687.41 ; 13121.17,687.41 ccw(c13121.17,706.7) v1@13134.81,693.06 ; 13121.57,687.41 cw(c13121.57,668.69) v1@13134.81,681.92 ; v1@13145.95,681.92 cw(c13159.19,668.69) 13159.19,687.41 ; v1@13145.95,693.06 ccw(c13159.59,706.7) 13159.59,687.41 ; 14446.09,687.41 ccw(c14446.09,706.54) v1@14459.61,693.01 ; 14446.26,687.41 cw(c14446.26,668.52) v1@14459.61,681.88 ; v1@14470.75,681.88 cw(c14484.11,668.52) 14484.11,687.41 ; v1@14470.75,693.01 ccw(c14484.27,706.54) 14484.27,687.41 ; v1@15581.66,628.13 cw(c15568.22,614.68) 15587.23,614.68 cw(c15606.24,614.68) v1@15592.8,628.13
  Bottom Layer w7.87: v1@314.93,631.56 cw(c301.49,618.12) 320.5,618.12 cw(c339.51,618.12) v1@326.06,631.56 ; LED92.B@320.5,598.62 v1(320.5,637.13) ; v1@1249.97,681.88 cw(c1236.53,668.43) 1255.54,668.43 cw(c1274.54,668.43) v1@1261.1,681.88 ; LED93.B@1255.54,598.62 v1(1255.54,687.44) ; v1@2185.01,681.86 cw(c2171.57,668.42) 2190.58,668.42 cw(c2209.58,668.42) v1@2196.14,681.86 ; LED94.B@2190.58,598.62 v1(2190.58,687.43) ; v1@4990.13,681.89 cw(c4976.68,668.44) 4995.69,668.44 cw(c5014.7,668.44) v1@5001.26,681.89 ; LED95.B@4995.69,598.62 v1(4995.69,687.45) ; v1@7795.24,681.94 cw(c7781.8,668.5) 7800.81,668.5 cw(c7819.82,668.5) v1@7806.38,681.94 ; LED96.B@7800.81,598.62 v1(7800.81,687.51) ; v1@8730.28,681.88 cw(c8716.84,668.43) 8735.85,668.43 cw(c8754.86,668.43) v1@8741.42,681.88 ; LED97.B@8735.85,598.62 v1(8735.85,687.44) ; v1@9665.32,681.87 cw(c9651.88,668.43) 9670.89,668.43 cw(c9689.9,668.43) v1@9676.46,681.87 ; LED98.B@9670.89,598.62 v1(9670.89,687.44) ; v1@10528.87,1691 cw(c10515.43,1677.56) 10534.44,1677.56 cw(c10553.45,1677.56) v1@10540,1691 ; v1(10534.44,1696.57) 10534.44,1148.06 10886.55,795.95 v1(10886.55,687.46) ; v1@10600.36,681.86 cw(c10586.92,668.42) 10605.93,668.42 cw(c10624.94,668.42) v1@10611.5,681.86 ; LED99.B@10605.93,598.62 v1(10605.93,687.43) ; v1@10880.98,693.03 ccw(c10867.54,706.47) 10886.55,706.47 ccw(c10905.56,706.47) v1@10892.12,693.03 ; v1(10945.88,1688.9) RR17.2@10995.5,1688.9 ; v1@10951.45,1683.33 cw(c10964.89,1669.89) 10964.89,1688.9 cw(c10964.89,1707.91) v1@10951.45,1694.47 ; v1@11638.75,681.87 cw(c11625.31,668.43) 11644.32,668.43 cw(c11663.32,668.43) v1@11649.88,681.87 ; LED100.B@11644.32,598.62 v1(11644.32,687.44) ; v1@12386.78,682.02 cw(c12373.34,668.58) 12392.35,668.58 cw(c12411.36,668.58) v1@12397.91,682.02 ; LED101.B@12392.35,598.62 v1(12392.35,687.58) ; v1@13134.81,681.92 cw(c13121.37,668.48) 13140.38,668.48 cw(c13159.39,668.48) v1@13145.95,681.92 ; LED102.B@13140.38,598.62 v1(13140.38,687.49) ; v1@14459.61,681.88 cw(c14446.17,668.43) 14465.18,668.43 cw(c14484.19,668.43) v1@14470.75,681.88 ; LED103.B@14465.18,598.62 v1(14465.18,687.44) ; v1@15581.66,628.13 cw(c15568.22,614.68) 15587.23,614.68 cw(c15606.24,614.68) v1@15592.8,628.13 ; LED104.B@15587.23,598.62 v1(15587.23,633.69)
CAPLED: 
CAPVCC: 
CB10: LED10.VDD LED27.VDD LED48.VDD LED69.VDD LED84.VDD LED96.VDD RC11.1 | length 7655.4
  Bottom Layer w7.87: LED27.VDD@7697.56,3518.01 cw(c7674.04,3494.49) 7707.31,3494.49 cw(c7740.57,3494.49) LED27.VDD@7717.05,3518.01 ; LED27.VDD@7707.31,3527.76 7707.31,3304.59 8026.23,2985.67 8414.5,2985.67 8440.63,2959.53 8440.63,2377.88 8627.64,2190.88 8627.64,1610.86 8603.54,1586.76 8421.12,1586.76 8253.62,1419.26 8253.62,966.94 8071.83,785.15 7857.65,785.15 7744.95,672.45 7744.95,547.92 7757.24,535.63 ; 7707.42,3472.36 7992.18,3472.36 8018.24,3498.42 8018.24,3799.46 8180.79,3962.02 8517.13,3962.02 8551.96,3996.85 8551.96,4151.3 8454.35,4248.91 LED10.VDD@8454.35,4476.58 ; LED96.VDD@7776.53,526.71 ccw(c7757.25,510.33) 7757.25,535.63 ; LED96.VDD@7776.53,544.55 cw(c7757.25,560.94) 7757.25,535.63 ; LED96.VDD@7800.81,535.63 7757.24,535.63 ; LED84.VDD@7884.57,1273.92 cw(c7861.05,1250.4) 7894.32,1250.4 cw(c7927.58,1250.4) LED84.VDD@7904.06,1273.92 ; LED84.VDD@7894.32,1283.66 7894.32,1236.41 7908.94,1221.79 8253.31,1221.79 ; RC11.1@8001.92,3719.3 cw(c7962.54,3679.92) 8018.24,3679.92 ; RC11.1@8001.92,3738.79 ccw(c7962.54,3778.17) 8018.24,3778.17 ; RC11.1@8007.49,3724.87 cw(c7981.55,3698.93) 8018.24,3698.93 ; RC11.1@8007.49,3733.22 ccw(c7981.55,3759.16) 8018.24,3759.16 ; RC11.1@8018.24,3711.63 cw(c8029.08,3711.63) RC11.1@8021.41,3719.3 ; RC11.1@8018.24,3746.45 ccw(c8029.08,3746.45) RC11.1@8021.41,3738.79 ; LED48.VDD@8071.58,2769.98 cw(c8048.06,2746.46) 8081.32,2746.46 cw(c8114.59,2746.46) LED48.VDD@8091.07,2769.98 ; LED48.VDD@8081.32,2779.73 8081.32,2733.65 8094.68,2720.29 8439.85,2720.29 ; LED69.VDD@8258.59,2021.95 cw(c8235.06,1998.43) 8268.33,1998.43 cw(c8301.6,1998.43) LED69.VDD@8278.07,2021.95 ; LED69.VDD@8268.33,2031.69 8268.33,1983.35 8279.76,1971.92 8627.51,1971.92
CB11: LED11.VDD LED28.VDD LED49.VDD LED70.VDD LED85.VDD LED97.VDD RC12.1 | length 7113.8
  Bottom Layer w7.87: LED28.VDD@8445.6,3518.01 cw(c8422.07,3494.49) 8455.34,3494.49 cw(c8488.61,3494.49) LED28.VDD@8465.08,3518.01 ; LED28.VDD@8455.34,3527.76 8455.34,3483.59 8469.19,3469.74 8814.49,3469.74 ; LED85.VDD@8632.6,1273.9 cw(c8609.07,1250.37) 8642.34,1250.37 cw(c8675.61,1250.37) LED85.VDD@8652.09,1273.9 ; LED85.VDD@8642.34,1283.64 8642.34,1240.18 8659.76,1222.76 9001.31,1222.76 ; LED97.VDD@8712.27,525.95 ccw(c8689.09,503.04) 8689.09,535.63 ; LED97.VDD@8712.27,545.32 cw(c8689.09,568.22) 8689.09,535.63 ; LED97.VDD@8735.85,535.63 8689.08,535.63 ; RC12.1@8754.78,3728.56 8814.3,3728.56 ; RC12.1@8764.52,3718.81 cw(c8788.04,3695.29) 8788.04,3728.56 cw(c8788.04,3761.82) RC12.1@8764.52,3738.3 ; LED49.VDD@8819.61,2769.98 cw(c8796.09,2746.46) 8829.35,2746.46 cw(c8862.62,2746.46) LED49.VDD@8839.1,2769.98 ; LED49.VDD@8829.35,2779.73 8829.35,2735.42 8845.39,2719.39 9187.51,2719.39 ; LED70.VDD@9006.62,2021.95 cw(c8983.1,1998.43) 9016.36,1998.43 cw(c9049.63,1998.43) LED70.VDD@9026.11,2021.95 ; LED70.VDD@9016.36,2031.69 9016.36,1984.5 9026.97,1973.88 9340.92,1973.88 ; LED11.VDD@9202.39,4476.58 9202.39,4318.31 9102.85,4218.77 9102.85,4025.81 9043.98,3966.94 8814.49,3737.46 8814.49,3469.74 ; 8689.08,535.63 8676.37,548.35 8676.37,746.14 8691.23,761 8989.81,761 9001.65,772.84 9001.65,1474.81 9149.83,1622.99 9299.85,1622.99 9375.67,1698.81 9375.67,1878.35 9342.56,1911.46 9342.56,2190.99 9188.66,2344.89 9188.66,2975.53 9173.41,2990.78 8833.89,2990.78 8814.49,3010.18 8814.49,3469.74
CB12: LED12.VDD LED29.VDD LED50.VDD LED71.VDD LED98.VDD RC13.1 | length 5867
  Bottom Layer w7.87: LED29.VDD@9193.63,3518.01 cw(c9170.1,3494.49) 9203.37,3494.49 cw(c9236.64,3494.49) LED29.VDD@9213.11,3518.01 ; LED29.VDD@9203.37,3527.76 9203.37,3482.93 9215.54,3470.76 9560.25,3470.76 ; RC13.1@9503.62,3728.75 9562.53,3728.75 ; RC13.1@9514.52,3718.31 cw(c9539.71,3693.13) 9539.71,3728.75 ; RC13.1@9514.52,3737.8 ccw(c9536.38,3759.66) 9536.38,3728.75 ; 9562.23,3527.76 9562.53,3528.05 ; LED50.VDD@9567.64,2769.98 cw(c9544.12,2746.46) 9577.39,2746.46 cw(c9610.65,2746.46) LED50.VDD@9587.13,2769.98 ; LED50.VDD@9577.39,2779.73 9577.39,2733.49 9590.07,2720.81 9934.69,2720.81 ; LED98.VDD@9670.89,535.63 9615.4,535.63 9606.79,544.24 9606.79,1210.52 9668.64,1272.37 9668.64,1775.1 9764.39,1870.85 LED71.VDD@9764.39,2031.69 9719.83,2031.69 9698.63,2052.89 9698.63,2298.03 9713.8,2313.2 9915.68,2313.2 9935.71,2333.22 9935.71,3029.65 9737.56,3227.79 9737.56,3411.46 9678.26,3470.76 9562.53,3470.76 9562.53,3528.05 ; LED12.VDD@9950.42,4476.58 9950.42,4324.81 9852.27,4226.66 9852.27,3923.44 9789.49,3860.66 9589.27,3860.66 9562.53,3833.91 9562.53,3728.75 ; 9562.53,3528.05 9562.53,3728.75
CB13: LED13.VDD LED30.VDD LED51.VDD LED86.VDD LED99.VDD RC14.1 | length 5387.1
  Bottom Layer w7.87: LED86.VDD@10035.16,1273.92 cw(c10011.64,1250.4) 10044.91,1250.4 cw(c10078.17,1250.4) LED86.VDD@10054.65,1273.92 ; LED86.VDD@10044.91,1283.66 10044.91,1247.23 10069.85,1222.29 10402.66,1222.29 ; LED30.VDD@10315.67,3518.01 cw(c10292.15,3494.49) 10325.42,3494.49 cw(c10358.68,3494.49) LED30.VDD@10335.16,3518.01 ; LED30.VDD@10325.42,3527.76 10325.42,3480.63 10336.45,3469.6 10684.17,3469.6 ; LED99.VDD@10582.41,525.89 ccw(c10558.88,502.37) 10558.88,535.63 ccw(c10558.88,568.9) LED99.VDD@10582.41,545.38 ; LED51.VDD@10605.49,2405.65 10541.8,2405.65 10530.23,2417.22 10530.23,3016.98 10684.57,3171.33 10684.57,3727.76 10684.57,3853.45 ; LED99.VDD@10605.93,535.63 10555.49,535.63 10535.79,555.33 10535.79,690.67 10403.23,823.24 10403.23,1772.9 10512.24,1881.91 10512.24,2152.94 10607.9,2248.6 LED51.VDD@10607.9,2405.71 ; RC14.1@10629.71,3851.03 10682.15,3851.03 10684.57,3853.45 ; LED13.VDD@10698.45,4476.58 10698.45,4237.94 10797.44,4138.95 10797.44,3966.31 10684.57,3853.45
CB14: LED14.VDD LED31.VDD LED52.VDD LED100.VDD RC15.1 | length 6982.1
  Top Layer w7.87: v1(10891.87,2975.67) v1@11585.67,2975.66 ; v1@10897.44,2970.1 cw(c10910.86,2956.68) 10910.86,2975.66 ; v1@10897.44,2981.24 ccw(c10910.9,2994.7) 10910.9,2975.66 ; 11571.43,2975.66 ccw(c11571.43,2998.18) v1@11587.35,2982.26 ; 11576.39,2975.66 cw(c11576.39,2960.16) v1@11587.35,2971.12
  Bottom Layer w7.87: v1@10886.3,2970.1 cw(c10872.86,2956.66) 10891.87,2956.66 cw(c10910.88,2956.66) v1@10897.44,2970.1 ; v1(10891.87,2975.67) 10891.87,2616.58 10977.01,2531.45 10977.01,2394.54 11124.51,2247.04 11124.51,2025.41 11061.39,1962.29 10724.37,1962.29 10603.03,1840.95 10603.03,1157.35 11152.14,608.24 11489.56,608.24 11562.17,535.63 LED100.VDD@11644.32,535.63 ; v1@11587.35,2971.12 cw(c11573.91,2957.68) 11592.92,2957.68 cw(c11611.93,2957.68) v1@11598.49,2971.12 ; v1@11592.92,2984.56 ccw(c11592.92,3003.57) 11606.36,2990.13 ccw(c11619.8,2976.69) v1@11600.79,2976.69 ; LED100.VDD@11620.79,525.89 ccw(c11597.27,502.37) 11597.27,535.63 ccw(c11597.27,568.9) LED100.VDD@11620.79,545.38 ; LED31.VDD@11634.57,3518.01 cw(c11611.05,3494.49) 11644.32,3494.49 cw(c11677.58,3494.49) LED31.VDD@11654.06,3518.01 ; LED31.VDD@11644.32,3527.76 11644.32,3317.38 11734.58,3227.12 11734.58,3118.35 v1(11592.92,2976.69) 11592.92,2793.77 11606.97,2779.73 LED52.VDD@11651.21,2779.73 ; 11644.49,3471.24 11896.75,3471.24 11948.5,3522.99 11948.5,3937.79 11643.03,4243.26 11643.03,4468.4 LED14.VDD@11651.21,4476.58 ; RC15.1@11937.95,3719.3 cw(c11912.47,3693.82) 11948.5,3693.82 ; RC15.1@11937.95,3738.79 ccw(c11912.47,3764.27) 11948.5,3764.27 ; 11948.5,3697.73 cw(c11979,3697.73) RC15.1@11957.43,3719.3 ; 11948.5,3760.35 ccw(c11979,3760.35) RC15.1@11957.43,3738.79
CB15: LED15.VDD LED32.VDD LED53.VDD LED87.VDD LED101.VDD RC16.1 | length 8556
  Top Layer w7.87: v1@12392.35,2736.62 v1(13797.91,2736.62) ; v1@12397.91,2730.89 cw(c12411.76,2717.05) 12411.76,2736.62 ; v1@12397.91,2742.02 ccw(c12410.96,2755.07) 12410.96,2736.62 ; v1(12751.5,1351.63) v1(13797.76,1351.63) ; v1@12757.07,1346.06 cw(c12770.51,1332.62) 12770.51,1351.63 cw(c12770.51,1370.64) v1@12757.07,1357.2 ; v1@13792.19,1346.06 ccw(c13778.75,1332.62) 13778.75,1351.63 ccw(c13778.75,1370.64) v1@13792.19,1357.2 ; v1@13792.34,2731.05 ccw(c13778.9,2717.61) 13778.9,2736.62 ccw(c13778.9,2755.63) v1@13792.34,2742.19
  Bottom Layer w7.87: LED53.VDD@12368.39,2770.43 ccw(c12347.31,2751.16) 12347.31,2779.73 ; LED53.VDD@12368.39,2789.02 cw(c12347.31,2808.29) 12347.31,2779.73 ; LED101.VDD@12382.6,525.89 cw(c12359.08,502.37) 12392.35,502.37 cw(c12425.61,502.37) LED101.VDD@12402.09,525.89 ; LED87.VDD@12382.6,1273.92 cw(c12359.08,1250.4) 12392.35,1250.4 cw(c12425.61,1250.4) LED87.VDD@12402.09,1273.92 ; LED32.VDD@12382.6,3518.01 cw(c12359.08,3494.49) 12392.35,3494.49 cw(c12425.61,3494.49) LED32.VDD@12402.09,3518.01 ; v1@12386.78,2742.02 ccw(c12373.34,2755.47) 12392.35,2755.47 ccw(c12411.36,2755.47) v1@12397.91,2742.02 ; LED101.VDD@12392.35,535.63 12392.35,488.21 12407.19,473.37 12665.26,473.37 12695.83,503.93 12695.83,888.48 12751.65,944.3 12751.65,1351.48 v1(12751.5,1351.63) ; LED87.VDD@12392.35,1283.66 12392.35,1240.56 12409.59,1223.31 12751.02,1223.31 ; v1(12392.35,2736.46) 12392.35,2779.73 12347.31,2779.73 ; 12392.36,3469.44 12675.35,3469.44 12702.29,3496.38 12702.29,3937.41 12399.24,4240.47 LED15.VDD@12399.24,4476.58 ; LED32.VDD@12392.35,3527.76 12392.35,3308.53 12392.48,3308.39 ; 12392.48,3400.09 12392.48,3308.39 ; RC16.1@12686.46,3718.81 cw(c12648.25,3680.61) 12702.29,3680.61 ; RC16.1@12686.46,3738.3 ccw(c12648.25,3776.51) 12702.29,3776.51 ; RC16.1@12692.03,3724.38 cw(c12667.26,3699.62) 12702.29,3699.62 ; RC16.1@12692.03,3732.73 ccw(c12667.26,3757.5) 12702.29,3757.5 ; 12702.29,3709.98 cw(c12714.79,3709.98) RC16.1@12705.95,3718.81 ; 12702.29,3747.14 ccw(c12714.79,3747.14) RC16.1@12705.95,3738.3 ; v1@12745.93,1346.06 cw(c12732.13,1332.26) 12751.65,1332.26 ; 12751.65,1332.98 cw(c12770.15,1332.98) v1@12757.07,1346.06 ; v1@13792.19,1357.2 ccw(c13778.39,1371) 13797.91,1371 ; v1@13792.34,2731.05 cw(c13778.9,2717.61) 13797.91,2717.61 cw(c13816.92,2717.61) v1@13803.48,2731.05 ; v1(13797.76,1351.63) 13797.91,1351.78 v1(13797.91,2736.62) ; 13797.91,1370.28 ccw(c13816.41,1370.28) v1@13803.33,1357.2 ; 12347.31,2779.73 12335.03,2792 12335.03,2960.81 12492.85,3118.63 12492.85,3208.02 12392.48,3308.39
CB16: LED16.VDD LED33.VDD LED54.VDD LED102.VDD RC17.1 | length 7131.9
  Top Layer w7.87: v1(13140.38,476.29) 13525.77,476.29 13561.69,440.36 v1(13819.72,440.36) ; v1(13140.38,2710.82) v1(13819.76,2710.82) ; v1@13145.95,470.72 cw(c13159.39,457.28) 13159.39,476.29 cw(c13159.39,495.3) v1@13145.95,481.85 ; v1@13145.95,2705.26 cw(c13159.39,2691.81) 13159.39,2710.82 cw(c13159.39,2729.83) v1@13145.95,2716.39 ; v1@13814.15,434.79 ccw(c13800.71,421.35) 13800.71,440.36 ccw(c13800.71,459.37) v1@13814.15,445.93 ; v1@13814.2,2705.26 ccw(c13800.75,2691.81) 13800.75,2710.82 ccw(c13800.75,2729.83) v1@13814.2,2716.39
  Bottom Layer w7.87: LED102.VDD@13130.63,525.89 cw(c13107.11,502.37) 13140.38,502.37 cw(c13173.65,502.37) LED102.VDD@13150.12,525.89 ; LED54.VDD@13130.63,2769.98 cw(c13107.11,2746.46) 13140.38,2746.46 cw(c13173.65,2746.46) LED54.VDD@13150.12,2769.98 ; LED33.VDD@13130.63,3518.01 cw(c13107.11,3494.49) 13140.38,3494.49 cw(c13173.65,3494.49) LED33.VDD@13150.12,3518.01 ; v1@13134.81,481.85 ccw(c13121.37,495.3) 13140.38,495.3 ccw(c13159.39,495.3) v1@13145.95,481.85 ; v1@13134.81,2716.39 ccw(c13121.37,2729.83) 13140.38,2729.83 ccw(c13159.39,2729.83) v1@13145.95,2716.39 ; v1(13140.38,476.29) LED102.VDD@13140.38,535.63 ; v1(13140.38,2710.82) 13140.38,2793.41 13098.43,2793.41 13086.25,2805.59 13086.25,3055.23 13100.53,3069.51 13460.12,3069.51 13499.53,3108.92 13499.53,3472.08 ; LED33.VDD@13140.38,3527.76 13140.38,3490.51 13158.81,3472.08 13499.53,3472.08 ; LED16.VDD@13147.27,4476.58 13147.27,4430.15 13158.99,4418.43 13472.95,4418.43 13499.53,4391.85 13499.53,3729.73 ; RC17.1@13447.38,3729.73 13499.53,3729.73 ; RC17.1@13456.93,3719.8 cw(c13480.92,3695.82) 13480.92,3729.73 ; RC17.1@13456.93,3739.29 ccw(c13480,3762.35) 13480,3729.73 ; v1@13814.15,445.93 ccw(c13800.71,459.37) 13819.72,459.37 ccw(c13838.72,459.37) v1@13825.28,445.93 ; v1@13814.2,2705.26 cw(c13800.87,2691.93) 13819.72,2691.93 ; v1(13819.72,440.36) v1@13819.72,2710.82 ; 13819.72,2691.7 cw(c13838.89,2691.7) v1@13825.33,2705.26 ; 13499.53,3472.08 13499.53,3729.73
CB17: LED34.VDD LED55.VDD LED72.VDD LED88.VDD RC18.1 | length 4461.3
  Bottom Layer w7.87: LED88.VDD@14081.42,1273.92 cw(c14057.9,1250.4) 14091.17,1250.4 cw(c14124.43,1250.4) LED88.VDD@14100.91,1273.92 ; LED72.VDD@14081.42,2021.95 cw(c14057.9,1998.43) 14091.17,1998.43 cw(c14124.43,1998.43) LED72.VDD@14100.91,2021.95 ; LED55.VDD@14081.42,2769.98 cw(c14057.9,2746.46) 14091.17,2746.46 cw(c14124.43,2746.46) LED55.VDD@14100.91,2769.98 ; LED34.VDD@14081.42,3518.01 cw(c14057.9,3494.49) 14091.17,3494.49 cw(c14124.43,3494.49) LED34.VDD@14100.91,3518.01 ; LED88.VDD@14091.17,1283.66 14091.17,1240.79 14104.89,1227.07 14418.63,1227.07 14450.47,1258.91 14450.47,2958.08 14091.17,3317.38 LED34.VDD@14091.17,3527.76 ; LED72.VDD@14091.17,2031.69 14091.17,1986.02 14104.21,1972.98 14449.21,1972.98 ; LED55.VDD@14091.17,2779.73 14091.17,2739.07 14109.15,2721.09 14450.09,2721.09 ; 14092.02,3470.46 14364.31,3470.46 14397.17,3503.32 RC18.1@14397.17,3729.7 ; RC18.1@14387.75,3720.28 cw(c14365,3697.54) 14397.17,3697.54 ; 14397.17,3695.98 cw(c14431.54,3695.98) RC18.1@14407.24,3720.28
CB18: LED35.VDD LED56.VDD LED73.VDD LED89.VDD LED103.VDD RC19.1 | length 5896.5
  Bottom Layer w7.87: LED103.VDD@14455.44,525.89 cw(c14431.91,502.37) 14465.18,502.37 cw(c14498.45,502.37) LED103.VDD@14474.92,525.89 ; LED103.VDD@14465.18,535.63 14465.18,485.85 14478.82,472.21 14614.67,472.21 14636.56,450.33 14797.49,450.33 14815.06,467.9 14815.06,729.38 15004.39,918.71 15148.31,918.71 15198.35,968.76 15198.35,1901.54 15128.62,1971.28 15128.62,2319.45 15198.35,2389.18 15198.35,2716.71 ; LED89.VDD@14829.45,1273.92 cw(c14805.93,1250.4) 14839.2,1250.4 cw(c14872.46,1250.4) LED89.VDD@14848.94,1273.92 ; LED73.VDD@14829.45,2021.95 cw(c14805.93,1998.43) 14839.2,1998.43 cw(c14872.46,1998.43) LED73.VDD@14848.94,2021.95 ; LED56.VDD@14829.45,2769.98 cw(c14805.93,2746.46) 14839.2,2746.46 cw(c14872.46,2746.46) LED56.VDD@14848.94,2769.98 ; LED35.VDD@14829.45,3518.01 cw(c14805.93,3494.49) 14839.2,3494.49 cw(c14872.46,3494.49) LED35.VDD@14848.94,3518.01 ; LED89.VDD@14839.2,1283.66 14839.2,1239.91 14855.13,1223.98 15197.52,1223.98 ; LED73.VDD@14839.2,2031.69 14839.2,1981.92 14849.32,1971.79 15128.62,1971.79 ; LED56.VDD@14839.2,2779.73 14839.2,2729.59 14851.05,2717.74 15197.32,2717.74 15198.35,2716.71 ; LED35.VDD@14839.2,3527.76 14839.2,3483.75 14856.33,3466.61 15198.35,3466.61 ; RC19.1@15143.56,3729.54 15170.15,3729.54 ; RC19.1@15154.82,3721.6 cw(c15170.15,3710.78) 15170.15,3729.54 ; RC19.1@15154.82,3737.49 ccw(c15170.15,3748.31) 15170.15,3729.54 ; 15170.15,3729.54 15198.35,3701.34 15198.35,3466.61 ; 15198.35,2716.71 15198.35,3466.61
